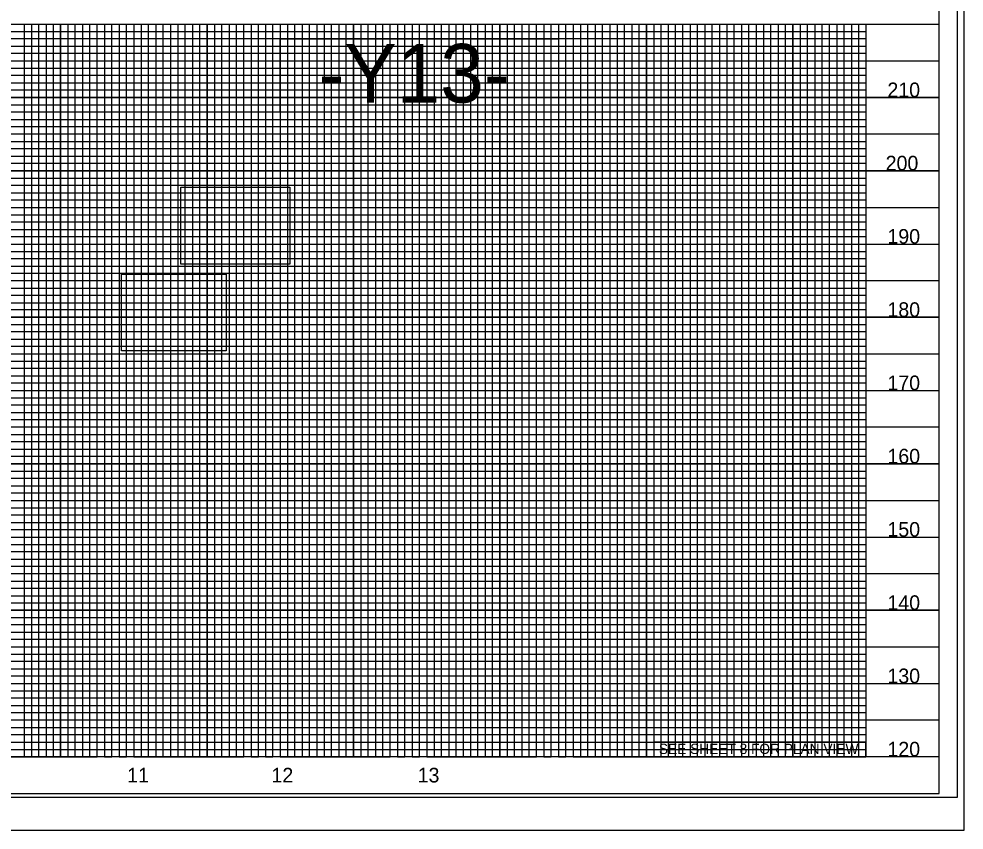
# Model space of a CAD drawing. Extents: x 1779926 to 1781610, y 605564 to 621564.
# Drawn here: x 1780964 to 1781610, y 605564 to 606118 of the extents above; entities that cross this region are included whole.
import ezdxf

# ---------------------------------------------------------------- set-up
doc = ezdxf.new("R2010")
doc.units = 0
for name, color, linetype in [('Exist Vertical Profile Horizontal Axis Label Major', 7, 'Continuous'), ('Exist Vertical Profile Vertical Axis Label', 7, 'Continuous'), ('Prop DSN Text', 7, 'Continuous'), ('Prop Grid Mask', 7, 'Continuous'), ('Scratch_Level_0', 7, 'Continuous'), ('Sheet DOT Grid CELL', 7, 'Continuous'), ('Sheet Layout Profile Border Port 2', 7, 'Continuous'), ('Sheet Plot Border Inside CELL', 7, 'Continuous'), ('Sheet Plot Border Outside CELL', 7, 'Continuous'), ('Sheet Profile CELL', 7, 'Continuous'), ('Sheet Profile Grid Major CELL', 7, 'Continuous'), ('Sheet Profile Grid Middle CELL', 7, 'Continuous'), ('Sheet Profile Grid Minor CELL', 7, 'Continuous')]:
    doc.layers.add(name, color=color, linetype=linetype)

msp = doc.modelspace()

# ---------------------------------------------------------------- linework, layer by layer
at = {"layer": 'Prop Grid Mask'}
for points in [[(1781142.96, 606104.2), (1781332.96, 606104.2), (1781332.96, 606054.2), (1781142.96, 606054.2)], [(1781075, 606002.95), (1781149.48, 606002.95), (1781149.48, 605950.43), (1781075, 605950.43)], [(1781034.49, 605943.66), (1781106.05, 605943.66), (1781106.05, 605891.25), (1781034.49, 605891.25)], [(1781542.96, 605624.2), (1781397.96, 605624.2), (1781397.96, 605614.2), (1781542.96, 605614.2)]]:
    msp.add_lwpolyline(points, close=True, dxfattribs=at)
at = {"layer": 'Scratch_Level_0'}
msp.add_lwpolyline([(1780142.96, 605614.2), (1780142.96, 606114.2), (1781542.96, 606114.2), (1781542.96, 605614.2)], close=True, dxfattribs=at)
at = {"layer": 'Sheet DOT Grid CELL'}
for p, q in [((1780092.96, 606114.2), (1781592.85, 606114.2)), ((1780992.96, 606114.2), (1780992.96, 605614.2)), ((1781042.96, 606114.2), (1781042.96, 605614.2)), ((1781092.96, 606114.2), (1781092.96, 605614.2)), ((1781142.96, 606114.2), (1781142.96, 605614.2)), ((1781192.96, 606114.2), (1781192.96, 605614.2)), ((1781242.96, 606114.2), (1781242.96, 605614.2)), ((1781292.96, 606114.2), (1781292.96, 605614.2)), ((1781342.96, 606114.2), (1781342.96, 605614.2)), ((1781392.96, 606114.2), (1781392.96, 605614.2)), ((1781442.96, 606114.2), (1781442.96, 605614.2)), ((1781492.96, 606114.2), (1781492.96, 605614.2)), ((1781542.96, 606114.2), (1781542.96, 605614.2)), ((1780092.96, 606064.2), (1781592.85, 606064.2)), ((1780092.96, 606014.2), (1781592.85, 606014.2)), ((1780092.96, 605964.2), (1781592.85, 605964.2)), ((1780092.96, 605914.2), (1781592.85, 605914.2)), ((1780092.96, 605864.2), (1781592.85, 605864.2)), ((1780092.96, 605814.2), (1781592.85, 605814.2)), ((1780092.96, 605764.2), (1781592.85, 605764.2)), ((1780092.96, 605714.2), (1781592.85, 605714.2)), ((1780092.96, 605664.2), (1781592.85, 605664.2))]:
    msp.add_line(p, q, dxfattribs=at)
at = {"layer": 'Sheet Layout Profile Border Port 2'}
msp.add_lwpolyline([(1780142.96, 606114.2), (1781542.96, 606114.2), (1781542.96, 605614.2), (1780142.96, 605614.2)], close=True, dxfattribs=at)
at = {"layer": 'Sheet Plot Border Inside CELL'}
msp.add_lwpolyline([(1779938.96, 605586.65), (1781605.46, 605586.65), (1781605.46, 606641.75), (1779938.96, 606641.75)], close=True, dxfattribs=at)
at = {"layer": 'Sheet Plot Border Outside CELL'}
msp.add_lwpolyline([(1779925.96, 605564.2), (1781609.96, 605564.2), (1781609.96, 606664.2), (1779925.96, 606664.2)], close=True, dxfattribs=at)
at = {"layer": 'Sheet Profile CELL'}
for p, q in [((1780092.96, 606114.2), (1781592.96, 606114.2)), ((1781592.96, 605614.2), (1780092.96, 605614.2)), ((1780092.96, 605589.2), (1781592.96, 605589.2))]:
    msp.add_line(p, q, dxfattribs=at)
msp.add_lwpolyline([(1781592.96, 606639.2), (1780092.96, 606639.2), (1780092.96, 605589.2), (1781592.96, 605589.2)], close=True, dxfattribs=at)
at = {"layer": 'Sheet Profile Grid Major CELL'}
for p, q in [((1780992.96, 606114.2), (1781042.96, 606114.2)), ((1781092.96, 606114.2), (1781142.96, 606114.2)), ((1781192.96, 606114.2), (1781242.96, 606114.2)), ((1781292.96, 606114.2), (1781342.96, 606114.2)), ((1781392.96, 606114.2), (1781442.96, 606114.2)), ((1781492.96, 606114.2), (1781542.96, 606114.2)), ((1781492.96, 605614.2), (1781492.96, 605614.2))]:
    msp.add_line(p, q, dxfattribs=at)
for points in [[(1780942.96, 605614.2), (1780992.96, 605614.2), (1780992.96, 606114.2), (1781042.96, 606114.2), (1781042.96, 605614.2), (1781092.96, 605614.2), (1781092.96, 606114.2), (1781142.96, 606114.2), (1781142.96, 605614.2), (1781192.96, 605614.2), (1781192.96, 606114.2), (1781242.96, 606114.2), (1781242.96, 605614.2), (1781292.96, 605614.2), (1781292.96, 606114.2), (1781342.96, 606114.2), (1781342.96, 605614.2), (1781392.96, 605614.2), (1781392.96, 606114.2), (1781442.96, 606114.2), (1781442.96, 605614.2), (1781492.96, 605614.2), (1781492.96, 605614.2), (1781492.96, 606114.2), (1781542.96, 606114.2), (1781542.96, 605614.2)], [(1781592.96, 606064.2), (1780092.96, 606064.2)], [(1781592.96, 606014.2), (1780092.96, 606014.2), (1780092.96, 605964.2), (1781592.96, 605964.2)], [(1781592.96, 605914.2), (1780092.96, 605914.2), (1780092.96, 605864.2), (1781592.96, 605864.2)], [(1781592.96, 605814.2), (1780092.96, 605814.2), (1780092.96, 605764.2), (1781592.96, 605764.2)], [(1781592.96, 605714.2), (1780092.96, 605714.2), (1780092.96, 605714.2), (1780092.96, 605664.2), (1781592.96, 605664.2)], [(1781592.96, 605614.2), (1780092.96, 605614.2)]]:
    msp.add_lwpolyline(points, dxfattribs=at)
at = {"layer": 'Sheet Profile Grid Middle CELL'}
for points in [[(1780917.96, 606114.2), (1780967.96, 606114.2), (1780967.96, 605614.2), (1781017.96, 605614.2), (1781017.96, 606114.2), (1781067.96, 606114.2), (1781067.96, 605614.2), (1781117.96, 605614.2), (1781117.96, 606114.2), (1781167.96, 606114.2), (1781167.96, 605614.2), (1781217.96, 605614.2), (1781217.96, 606114.2), (1781267.96, 606114.2), (1781267.96, 605614.2), (1781317.96, 605614.2), (1781317.96, 606114.2), (1781367.96, 606114.2), (1781367.96, 605614.2), (1781417.96, 605614.2), (1781417.96, 606114.2), (1781467.96, 606114.2), (1781467.96, 605614.2), (1781517.96, 605614.2), (1781517.96, 606114.2)], [(1780092.96, 606089.2), (1781592.96, 606089.2)], [(1781592.96, 606039.2), (1780092.96, 606039.2), (1780092.96, 605989.2), (1781592.96, 605989.2)], [(1781592.96, 605939.2), (1780092.96, 605939.2), (1780092.96, 605889.2), (1781592.96, 605889.2)], [(1781592.96, 605839.2), (1780092.96, 605839.2), (1780092.96, 605789.2), (1781592.96, 605789.2)], [(1781592.96, 605739.2), (1780092.96, 605739.2), (1780092.96, 605689.2), (1781592.96, 605689.2)], [(1781592.96, 605639.2), (1780092.96, 605639.2)]]:
    msp.add_lwpolyline(points, dxfattribs=at)
at = {"layer": 'Sheet Profile Grid Minor CELL'}
for p, q in [((1780142.96, 606109.2), (1781542.96, 606109.2)), ((1781542.96, 606104.2), (1780142.96, 606104.2)), ((1780142.96, 606099.2), (1781542.96, 606099.2)), ((1781542.96, 606094.2), (1780142.96, 606094.2)), ((1780142.96, 606084.2), (1781542.96, 606084.2)), ((1781542.96, 606079.2), (1780142.96, 606079.2)), ((1780142.96, 606074.2), (1781542.96, 606074.2)), ((1781542.96, 606069.2), (1780142.96, 606069.2)), ((1780142.96, 606059.2), (1781542.96, 606059.2)), ((1781542.96, 606054.2), (1780142.96, 606054.2)), ((1780142.96, 606049.2), (1781542.96, 606049.2)), ((1781542.96, 606044.2), (1780142.96, 606044.2)), ((1780142.96, 606034.2), (1781542.96, 606034.2)), ((1781542.96, 606029.2), (1780142.96, 606029.2)), ((1780142.96, 606024.2), (1781542.96, 606024.2)), ((1781542.96, 606019.2), (1780142.96, 606019.2)), ((1780142.96, 606009.2), (1781542.96, 606009.2)), ((1781542.96, 606004.2), (1780142.96, 606004.2)), ((1780142.96, 605999.2), (1781542.96, 605999.2)), ((1781542.96, 605994.2), (1780142.96, 605994.2)), ((1780142.96, 605984.2), (1781542.96, 605984.2)), ((1781542.96, 605979.2), (1780142.96, 605979.2)), ((1780142.96, 605974.2), (1781542.96, 605974.2)), ((1781542.96, 605969.2), (1780142.96, 605969.2)), ((1780142.96, 605959.2), (1781542.96, 605959.2)), ((1781542.96, 605954.2), (1780142.96, 605954.2)), ((1780142.96, 605949.2), (1781542.96, 605949.2)), ((1781542.96, 605944.2), (1780142.96, 605944.2)), ((1780142.96, 605934.2), (1781542.96, 605934.2)), ((1781542.96, 605929.2), (1780142.96, 605929.2)), ((1780142.96, 605924.2), (1781542.96, 605924.2)), ((1781542.96, 605919.2), (1780142.96, 605919.35)), ((1780142.96, 605909.2), (1781542.96, 605909.2)), ((1781542.96, 605904.2), (1780142.96, 605904.2)), ((1780142.96, 605899.2), (1781542.96, 605899.2)), ((1781542.96, 605894.2), (1780142.96, 605894.2)), ((1780142.96, 605884.2), (1781542.96, 605884.2)), ((1781542.96, 605879.2), (1780142.96, 605879.2)), ((1780142.96, 605874.2), (1781542.96, 605874.2)), ((1781542.96, 605869.2), (1780142.96, 605869.2)), ((1780142.96, 605859.2), (1781542.96, 605859.2)), ((1781542.96, 605854.2), (1780142.96, 605854.2)), ((1780142.96, 605849.2), (1781542.96, 605849.2)), ((1781542.96, 605844.2), (1780142.96, 605844.2)), ((1780142.96, 605834.2), (1781542.96, 605834.2)), ((1781542.96, 605829.2), (1780142.96, 605829.2)), ((1780142.96, 605824.2), (1781542.96, 605824.2)), ((1781542.96, 605819.2), (1780142.96, 605819.2)), ((1780142.96, 605809.2), (1781542.96, 605809.2)), ((1781542.96, 605804.2), (1780142.96, 605804.2)), ((1780142.96, 605799.2), (1781542.96, 605799.2)), ((1781542.96, 605794.2), (1780142.96, 605794.2)), ((1780142.96, 605784.2), (1781542.96, 605784.2)), ((1781542.96, 605779.2), (1780142.96, 605779.2)), ((1780142.96, 605774.2), (1781542.96, 605774.2)), ((1781542.96, 605769.2), (1780142.96, 605769.2)), ((1780142.96, 605759.2), (1781542.96, 605759.2)), ((1781542.96, 605754.2), (1780142.96, 605754.2)), ((1780142.96, 605749.2), (1781542.96, 605749.2)), ((1781542.96, 605744.2), (1780142.96, 605744.2)), ((1780142.96, 605734.2), (1781542.96, 605734.2)), ((1781542.96, 605729.2), (1780142.96, 605729.2)), ((1780142.96, 605724.2), (1781542.96, 605724.2)), ((1781542.96, 605719.2), (1780142.96, 605719.2)), ((1780142.96, 605709.2), (1781542.96, 605709.2)), ((1781542.96, 605704.2), (1780142.96, 605704.2)), ((1780142.96, 605699.2), (1781542.96, 605699.2)), ((1781542.96, 605694.2), (1780142.96, 605694.2)), ((1780142.96, 605684.2), (1781542.96, 605684.2)), ((1781542.96, 605679.2), (1780142.96, 605679.2)), ((1780142.96, 605674.2), (1781542.96, 605674.2)), ((1781542.96, 605669.2), (1780142.96, 605669.2)), ((1780142.96, 605659.2), (1781542.96, 605659.2)), ((1781542.96, 605654.2), (1780142.96, 605654.2)), ((1780142.96, 605649.2), (1781542.96, 605649.2)), ((1781542.96, 605644.2), (1780142.96, 605644.2)), ((1780142.96, 605634.2), (1781542.96, 605634.2)), ((1781542.96, 605629.2), (1780142.96, 605629.2)), ((1780142.96, 605624.2), (1781542.96, 605624.2)), ((1780142.96, 605619.2), (1781542.96, 605619.2)), ((1781542.96, 605619.2), (1781542.96, 605619.2))]:
    msp.add_line(p, q, dxfattribs=at)
for points in [[(1780962.96, 606114.2), (1780972.96, 606114.2), (1780972.96, 605614.2), (1780977.96, 605614.2)], [(1780977.96, 605614.2), (1780977.96, 606114.2), (1780982.96, 606114.2), (1780982.96, 605614.2), (1780987.96, 605614.2), (1780987.96, 606114.2), (1780997.96, 606114.2), (1780997.96, 605614.2), (1781002.96, 605614.2), (1781002.96, 606114.2), (1781007.96, 606114.2), (1781007.96, 605614.2), (1781012.96, 605614.2), (1781012.96, 606114.2), (1781022.96, 606114.2), (1781022.96, 605614.2), (1781027.96, 605614.2), (1781027.96, 606114.2), (1781032.96, 606114.2), (1781032.96, 605614.2), (1781037.96, 605614.2), (1781037.96, 606114.2), (1781047.96, 606114.2), (1781047.96, 605614.2), (1781052.96, 605614.2), (1781052.96, 606114.2), (1781057.96, 606114.2), (1781057.96, 605614.2), (1781062.96, 605614.2), (1781062.96, 606114.2), (1781072.96, 606114.2), (1781072.96, 605614.2), (1781077.96, 605614.2), (1781077.96, 606114.2), (1781082.96, 606114.2), (1781082.96, 605614.2), (1781087.96, 605614.2), (1781087.96, 606114.2), (1781097.96, 606114.2), (1781097.96, 605614.2), (1781102.96, 605614.2), (1781102.96, 606114.2), (1781107.96, 606114.2), (1781107.96, 605614.2), (1781112.96, 605614.2), (1781112.96, 606114.2), (1781122.96, 606114.2), (1781122.96, 605614.2), (1781127.96, 605614.2), (1781127.96, 606114.2), (1781132.96, 606114.2), (1781132.96, 605614.2), (1781137.96, 605614.2), (1781137.96, 606114.2), (1781147.96, 606114.2), (1781147.96, 605614.2), (1781152.96, 605614.2), (1781152.96, 606114.2), (1781157.96, 606114.2), (1781157.96, 605614.2), (1781162.96, 605614.2), (1781162.96, 606114.2), (1781172.96, 606114.2), (1781172.96, 605614.2), (1781177.96, 605614.2), (1781177.96, 606114.2), (1781182.96, 606114.2), (1781182.96, 605614.2), (1781187.96, 605614.2), (1781187.96, 606114.2), (1781197.96, 606114.2), (1781197.96, 605614.2), (1781202.96, 605614.2), (1781202.96, 606114.2), (1781207.96, 606114.2), (1781207.96, 605614.2), (1781212.96, 605614.2), (1781212.96, 606114.2), (1781222.96, 606114.2), (1781222.96, 605614.2), (1781227.96, 605614.2), (1781227.96, 606114.2), (1781232.96, 606114.2), (1781232.96, 605614.2), (1781237.96, 605614.2), (1781237.96, 606114.2), (1781247.96, 606114.2), (1781247.96, 605614.2), (1781252.96, 605614.2), (1781252.96, 606114.2), (1781257.96, 606114.2), (1781257.96, 605614.2), (1781262.96, 605614.2), (1781262.96, 606114.2), (1781272.96, 606114.2), (1781272.96, 605614.2), (1781277.96, 605614.2), (1781277.96, 606114.2), (1781282.96, 606114.2), (1781282.96, 605614.2)], [(1781282.96, 605614.2), (1781287.96, 605614.2), (1781287.96, 606114.2), (1781297.96, 606114.2), (1781297.96, 605614.2), (1781302.96, 605614.2), (1781302.96, 606114.2), (1781307.96, 606114.2), (1781307.96, 605614.2), (1781312.96, 605614.2), (1781312.96, 606114.2), (1781322.96, 606114.2), (1781322.96, 605614.2), (1781327.96, 605614.2), (1781327.96, 606114.2), (1781332.96, 606114.2), (1781332.96, 605614.2), (1781337.96, 605614.2), (1781337.96, 606114.2), (1781347.96, 606114.2), (1781347.96, 605614.2), (1781352.96, 605614.2), (1781352.96, 606114.2), (1781357.96, 606114.2), (1781357.96, 605614.2), (1781362.96, 605614.2), (1781362.96, 606114.2), (1781372.96, 606114.2), (1781372.96, 605614.2), (1781377.96, 605614.2), (1781377.96, 606114.2), (1781382.96, 606114.2), (1781382.96, 605614.2), (1781387.96, 605614.2), (1781387.96, 606114.2), (1781397.96, 606114.2), (1781397.96, 605614.2), (1781402.96, 605614.2), (1781402.96, 606114.2), (1781407.96, 606114.2), (1781407.96, 605614.2), (1781412.96, 605614.2), (1781412.96, 606114.2), (1781422.96, 606114.2), (1781422.96, 605614.2), (1781427.96, 605614.2), (1781427.96, 606114.2), (1781432.96, 606114.2), (1781432.96, 605614.2), (1781437.96, 605614.2), (1781437.96, 606114.2), (1781447.96, 606114.2), (1781447.96, 605614.2), (1781452.96, 605614.2), (1781452.96, 606114.2), (1781457.96, 606114.2), (1781457.96, 605614.2), (1781462.96, 605614.2), (1781462.96, 606114.2), (1781472.96, 606114.2), (1781472.96, 605614.2), (1781477.96, 605614.2), (1781477.96, 606114.2), (1781482.96, 606114.2), (1781482.96, 605614.2), (1781487.96, 605614.2), (1781487.96, 606114.2), (1781497.96, 606114.2), (1781497.96, 605614.2), (1781502.96, 605614.2), (1781502.96, 606114.2), (1781507.96, 606114.2), (1781507.96, 605614.2), (1781512.96, 605614.2), (1781512.96, 606114.2), (1781522.96, 606114.2), (1781522.96, 605614.2), (1781527.96, 605614.2), (1781527.96, 606114.2), (1781532.96, 606114.2), (1781532.96, 605614.2), (1781537.96, 605614.2), (1781537.96, 606114.2), (1781542.96, 606114.2)]]:
    msp.add_lwpolyline(points, dxfattribs=at)

# ---------------------------------------------------------------- texts
at = {"layer": 'Exist Vertical Profile Horizontal Axis Label Major'}
for s, p in [('11', (1781038.38, 605596.7)), ('12', (1781136.93, 605596.7)), ('13', (1781236.77, 605596.7))]:
    msp.add_text(s, height=10, dxfattribs=at).set_placement(p)
at = {"layer": 'Exist Vertical Profile Vertical Axis Label'}
for s, height, p in [('-Y13-', 40, (1781168.96, 606060.79)), ('210', 10, (1781557.59, 606064.45)), ('200', 10, (1781556.39, 606014.45)), ('190', 10, (1781557.59, 605964.45)), ('180', 10, (1781557.59, 605914.45)), ('170', 10, (1781557.59, 605864.45)), ('160', 10, (1781557.59, 605814.45)), ('150', 10, (1781557.59, 605764.45)), ('140', 10, (1781557.59, 605714.45)), ('130', 10, (1781557.59, 605664.45)), ('120', 10, (1781557.59, 605614.45))]:
    msp.add_text(s, height=height, dxfattribs=at).set_placement(p)
at = {"layer": 'Prop DSN Text'}
msp.add_text('SEE SHEET 8 FOR PLAN VIEW', height=7, dxfattribs=at).set_placement((1781401.52, 605616.15))

doc.saveas('drawing.dxf')
